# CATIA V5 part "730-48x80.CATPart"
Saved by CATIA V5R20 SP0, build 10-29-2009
Part number: 730-48x80
Definition: NONE
Nomenclature: 730-48x80
Source: Unknown
Description: 730-48x80
Bounding box of the stored display mesh (mm): x -28 to 28, y -27.5 to 27.5, z 0 to 80
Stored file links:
  C:\Users\Utente\Desktop\IO LAVORO\3D X SITO CF\X SITO\730\730-48x80.CATPart
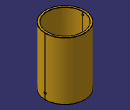
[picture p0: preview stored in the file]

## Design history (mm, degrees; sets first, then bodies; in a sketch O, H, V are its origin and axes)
Body1 "730-48x80" (main body)
  Solid1: solid without history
